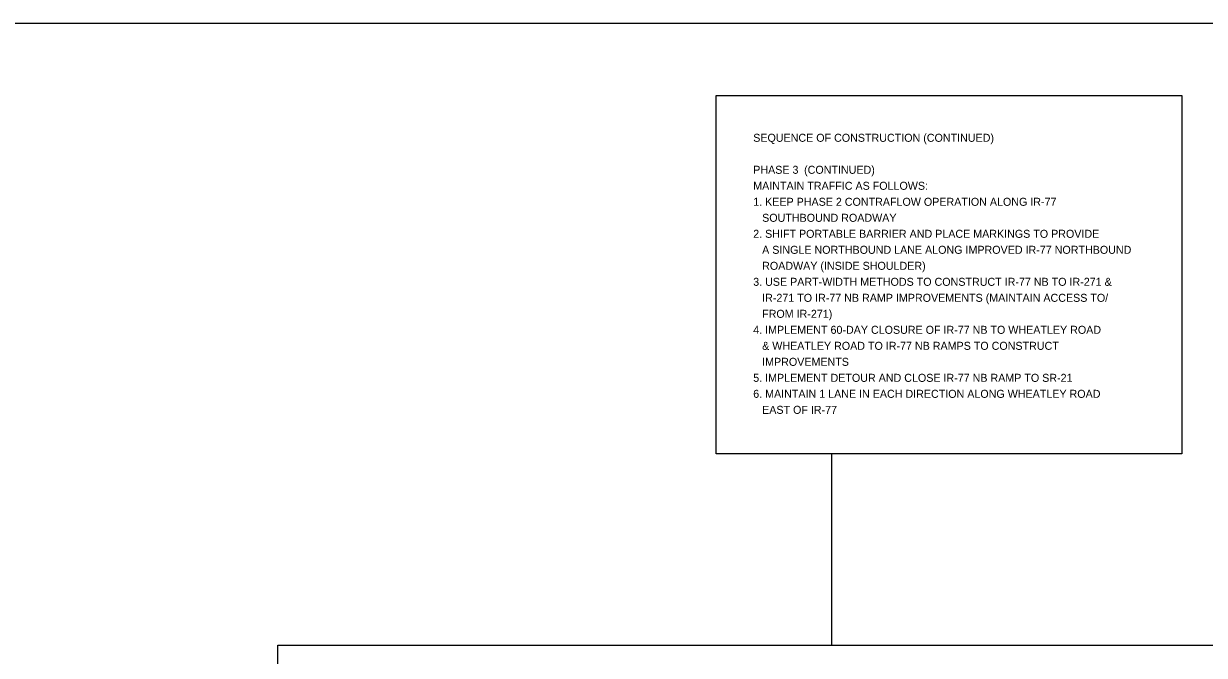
# Model space of a CAD drawing. Extents: x 1820207 to 1820557, y 740216 to 740315.
# Drawn here: x 1820256.95 to 1820277.6, y 740275.57 to 740286.62 of the extents above; entities that cross this region are included whole.
import ezdxf

# ---------------------------------------------------------------- set-up
doc = ezdxf.new("R2010")
doc.units = 0
for name, color, linetype in [('SC_Scratch2', 7, 'Continuous'), ('SC_Scratch4', 7, 'Continuous'), ('SH_Text', 7, 'Continuous')]:
    doc.layers.add(name, color=color, linetype=linetype)

msp = doc.modelspace()

# ---------------------------------------------------------------- linework, layer by layer
at = {"layer": 'SC_Scratch2'}
msp.add_lwpolyline([(1820261.39, 740275.742), (1820291.89, 740275.742), (1820291.89, 740254.742), (1820261.39, 740254.742)], close=True, dxfattribs=at)
at = {"layer": 'SC_Scratch4'}
msp.add_line((1820271.081, 740279.095), (1820271.081, 740275.742), dxfattribs=at)
msp.add_lwpolyline([(1820269.059, 740285.363), (1820277.209, 740285.363), (1820277.209, 740279.095), (1820269.059, 740279.095)], close=True, dxfattribs=at)
at = {"layer": 'SH_Text'}
msp.add_lwpolyline([(1820217.201, 740244.009), (1820515.724, 740244.009), (1820515.724, 740286.62), (1820217.201, 740286.62)], close=True, dxfattribs=at)

# ---------------------------------------------------------------- texts
for s, p in [('SEQUENCE OF CONSTRUCTION (CONTINUED)', (1820269.71, 740284.552)), ('PHASE 3', (1820269.71, 740283.992)), (' (CONTINUED)', (1820270.548, 740283.992)), ('MAINTAIN TRAFFIC AS FOLLOWS:', (1820269.71, 740283.712)), ('1. KEEP PHASE 2 CONTRAFLOW OPERATION ALONG IR-77 ', (1820269.71, 740283.432)), ('   SOUTHBOUND ROADWAY', (1820269.71, 740283.152)), ('2. SHIFT PORTABLE BARRIER AND PLACE MARKINGS TO PROVIDE ', (1820269.71, 740282.872)), ('   A SINGLE NORTHBOUND LANE ALONG IMPROVED IR-77 NORTHBOUND ', (1820269.71, 740282.592)), ('   ROADWAY (INSIDE SHOULDER)', (1820269.71, 740282.312)), ('3. USE PART-WIDTH METHODS TO CONSTRUCT IR-77 NB TO IR-271 & ', (1820269.71, 740282.032)), ('   IR-271 TO IR-77 NB RAMP IMPROVEMENTS (MAINTAIN ACCESS TO/', (1820269.71, 740281.752)), ('   FROM IR-271)', (1820269.71, 740281.472)), ('4. IMPLEMENT 60-DAY CLOSURE OF IR-77 NB TO WHEATLEY ROAD', (1820269.71, 740281.192)), ('   & WHEATLEY ROAD TO IR-77 NB RAMPS TO CONSTRUCT ', (1820269.71, 740280.912)), ('   IMPROVEMENTS', (1820269.71, 740280.632)), ('5. IMPLEMENT DETOUR AND CLOSE IR-77 NB RAMP TO SR-21', (1820269.71, 740280.352)), ('6. MAINTAIN 1 LANE IN EACH DIRECTION ALONG WHEATLEY ROAD', (1820269.71, 740280.072)), ('   EAST OF IR-77', (1820269.71, 740279.792))]:
    msp.add_text(s, height=0.14, rotation=360, dxfattribs=at).set_placement(p)

doc.saveas('drawing.dxf')
